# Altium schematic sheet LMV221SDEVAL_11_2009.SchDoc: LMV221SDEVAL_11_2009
size A4; Date: 02-Jan-07; DrawnBy: J. de Koning; Address1: Delftechpark 19; Address2: 2628 XJ; Address3: Delft; Address4: The Netherlands; Revision: A; SheetNumber: 1; SheetTotal: 1; Part: LMV221; PageSetup: Record=PageOptions|CenterHorizontal=True|CenterVertical=True|PrintScale=1.00|XCorrection=1.00|YCorrection=1.00|PrintKind=0|BorderSize=5000000|LeftOffset=0|BottomOffset=0|Orientation=2|PaperLength=1000|PaperWidth=1000|Scale=100|PaperSource=7|PrintQuality=-4|MediaType=1|DitherType=10|PaperKind=Letter|PrintScaleMode=1; Funktion: Evaluation
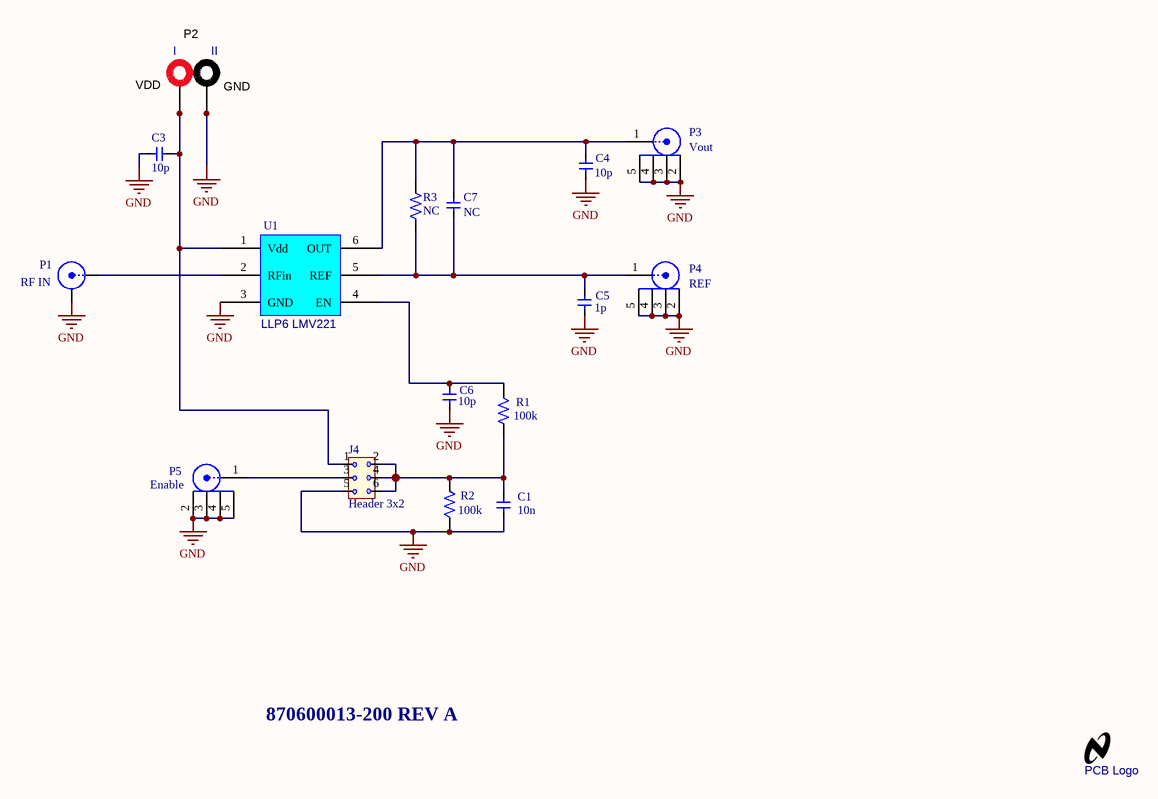
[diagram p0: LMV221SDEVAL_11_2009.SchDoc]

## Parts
C1  10n  [SM/RC_0603]
C3  10p  [C_SMD_201]
C4  10p  [C_SMD_201]
C5  1p  [C_SMD_201]
C6  10p  [C_SMD_201]
C7  NC  [SM/RC_0603]
I  571-0500  [571-0500]  (value not drawn)
II  571-0100  [571-0100]  (value not drawn)
J4  Header 3x2  [HDR2X3]
Logo1  PCB Logo  [Logo_Overlay_Medium]  (no BOM)
P1  RF IN  [SMA-SIDE]
P3  Vout  [5413631-2]
P4  REF  [5413631-2]
P5  Enable  [5413631-2]
R1  100k  [SM/RC_0603]
R2  100k  [SM/RC_0603]
R3  NC  [SM/RC_0603]
U1  LLP6 LMV221  [SDB06A]

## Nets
GND: C1.1 C3.1 C4.1 C5.2 C6.1 II.1 II.2 J4.5 P1.2(Y) P3.2 P3.3 P3.4 P3.5 P4.2 P4.3 P4.4 P4.5 P5.2 P5.3 P5.4 P5.5 R2.1 U1.3(GND) U1.7(DAP)
NetC1_2: C1.2 J4.2 J4.4 J4.6 R1.2 R2.2
NetC3_2: C3.2 I.1 I.2 J4.1 U1.1(Vdd)
NetC4_2: C4.2 C7.2 P3.1 R3.2 U1.6(OUT)
NetC5_1: C5.1 C7.1 P4.1 R3.1 U1.5(REF)
NetC6_2: C6.2 R1.1 U1.4(EN)
NetJ4_3: J4.3 P5.1
NetP1_1: P1.1(X) U1.2(RFin)

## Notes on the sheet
- (near I) VDD
- P2
- (near II) GND
- 870600013-200 REV A

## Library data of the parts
C1 = C smd: PSpiceTemplate: C^@REFDES %1 %2 ?TOLERANCE|C^@REFDES| @VALUE ?IC/IC=@IC/ ?TOLERANCE|\n.model C^@REFDES CAP C=1 DEV=@TOLERANCE%|; TOLERANCE: 10%; voltage: 16V
C3-C7 = C smd: TOLERANCE: 10%; PSpiceTemplate: C^@REFDES %1 %2 ?TOLERANCE|C^@REFDES| @VALUE ?IC/IC=@IC/ ?TOLERANCE|\n.model C^@REFDES CAP C=1 DEV=@TOLERANCE%|; voltage: 16V
I = 571-0500: Standard Banana Jack, insulated, 10A, red; Manufacturer: Deltron Emcon; CompType: Connector; SymbolCreator: codlsc
II = 571-0100: Standard Banana Jack, insulated, 10A, black; Manufacturer: Deltron Emcon; CompType: Connector; SymbolCreator: codlsc
J4 = Header N2 3x2
Logo1 = NSC Logo: National Semiconductor logo or worldmark; SymbolCreator: codlsc
P1 = SMA: SMA Connector
P3-P5 = 5413631-2: Connector, TH, BNC Right angle, 50 Ohm gold; Manufacturer: Amp
R1 R2 = R smd: PSpiceTemplate: R^@REFDES %1 %2 ?TOLERANCE|R^@REFDES| @VALUE  ?TOLERANCE|\n.model R^@REFDES RES R=1 DEV=@TOLERANCE%|; TOLERANCE: 1%
R3 = R smd: TOLERANCE: 1%; PSpiceTemplate: R^@REFDES %1 %2 ?TOLERANCE|R^@REFDES| @VALUE  ?TOLERANCE|\n.model R^@REFDES RES R=1 DEV=@TOLERANCE%|
U1 = LLP6 Fixture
